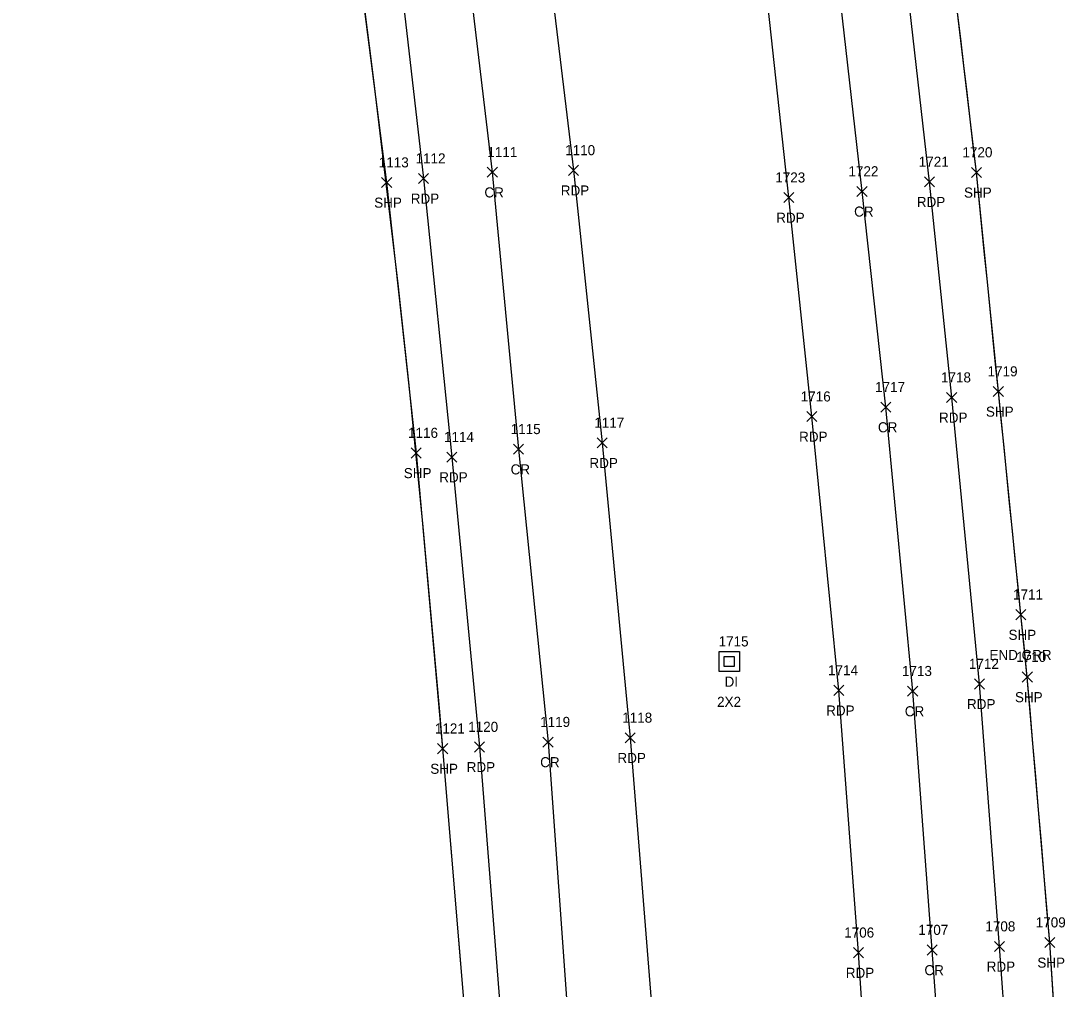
# Model space of a CAD drawing. Extents: x 1472022 to 1479249, y 777216 to 786527.
# Drawn here: x 1473815.7 to 1474023.2, y 781934.6 to 782126.8 of the extents above; entities that cross this region are included whole.
import ezdxf

# ---------------------------------------------------------------- set-up
doc = ezdxf.new("R2010")
doc.units = 0
for name, color, linetype in [('D_A', 7, 'Continuous'), ('D_C', 7, 'Continuous'), ('D_I', 7, 'Continuous'), ('DS', 7, 'Continuous'), ('LSOGP', 7, 'Continuous'), ('P_A', 7, 'Continuous'), ('P_C', 7, 'Continuous'), ('P_I', 7, 'Continuous'), ('P_TIC', 7, 'Continuous'), ('PET', 7, 'Continuous'), ('PRC', 7, 'Continuous'), ('PSP', 7, 'Continuous')]:
    doc.layers.add(name, color=color, linetype=linetype)

msp = doc.modelspace()

# ---------------------------------------------------------------- linework, layer by layer
at = {"layer": 'DS'}
for p, q in [((1473954.34, 782001.6), (1473958.34, 782001.6)), ((1473954.34, 781997.6), (1473954.34, 782001.6)), ((1473955.34, 781998.6), (1473955.34, 782000.6)), ((1473955.34, 782000.6), (1473957.34, 782000.6)), ((1473957.34, 782000.6), (1473957.34, 781998.6)), ((1473958.34, 782001.6), (1473958.34, 781997.6)), ((1473957.34, 781998.6), (1473955.34, 781998.6)), ((1473956.34, 781999.6), (1473956.34, 781999.6)), ((1473956.34, 781999.6), (1473956.34, 781999.6)), ((1473958.34, 781997.6), (1473954.34, 781997.6))]:
    msp.add_line(p, q, dxfattribs=at)
at = {"layer": 'LSOGP'}
for points in [[(1473883.98, 782128.59), (1473884.85, 782121.82), (1473885.71, 782115.04), (1473890.52, 782074.57), (1473891.25, 782067.86), (1473891.98, 782061.15), (1473892.72, 782054.44), (1473895.5, 782026.34), (1473896.16, 782019), (1473896.81, 782011.66), (1473897.47, 782004.33), (1473898.13, 781996.99), (1473898.79, 781989.65), (1473899.44, 781982.31), (1473900.03, 781975.19), (1473900.62, 781968.07), (1473901.21, 781960.95), (1473901.8, 781953.82), (1473902.39, 781946.7), (1473902.98, 781939.58), (1473903.57, 781932.45)], [(1474020.77, 781931.24), (1474020.37, 781937.53), (1474019.96, 781943.82), (1474019.4, 781950.41), (1474018.85, 781957), (1474018.29, 781963.59), (1474017.74, 781970.18), (1474017.18, 781976.76), (1474016.62, 781983.35), (1474016.07, 781989.94), (1474015.51, 781996.53), (1474014.87, 782002.72), (1474014.23, 782008.91), (1474013.67, 782014.45), (1474013.11, 782019.99), (1474012.55, 782025.53), (1474012, 782031.06), (1474011.44, 782036.6), (1474010.88, 782042.14), (1474010.32, 782047.68), (1474009.76, 782053.22), (1474009.21, 782058.66), (1474008.67, 782064.09), (1474008.13, 782069.53), (1474007.58, 782074.97), (1474007.04, 782080.4), (1474006.49, 782085.84), (1474005.95, 782091.28), (1474005.41, 782096.71), (1474004.78, 782102.01), (1474004.16, 782107.31), (1474003.54, 782112.61), (1474002.91, 782117.91), (1474002.29, 782123.21), (1474001.66, 782128.51)]]:
    msp.add_lwpolyline(points, dxfattribs=at)
at = {"layer": 'P_TIC'}
for points in [[(1473908.3, 782095.74), (1473910.3, 782097.74)], [(1473910.3, 782095.74), (1473908.3, 782097.74)], [(1473924.4, 782096.13), (1473926.4, 782098.13)], [(1473926.4, 782096.13), (1473924.4, 782098.13)], [(1474004.41, 782095.71), (1474006.41, 782097.71)], [(1474006.41, 782095.71), (1474004.41, 782097.71)], [(1473887.32, 782093.71), (1473889.32, 782095.71)], [(1473889.32, 782093.71), (1473887.32, 782095.71)], [(1473894.62, 782094.5), (1473896.62, 782096.5)], [(1473896.62, 782094.5), (1473894.62, 782096.5)], [(1473995.08, 782093.84), (1473997.08, 782095.84)], [(1473997.08, 782093.84), (1473995.08, 782095.84)], [(1473981.69, 782091.94), (1473983.69, 782093.94)], [(1473983.69, 782091.94), (1473981.69, 782093.94)], [(1473967.17, 782090.71), (1473969.17, 782092.71)], [(1473969.17, 782090.71), (1473967.17, 782092.71)], [(1474008.76, 782052.22), (1474010.76, 782054.22)], [(1474010.76, 782052.22), (1474008.76, 782054.22)], [(1473999.49, 782051.02), (1474001.49, 782053.02)], [(1474001.49, 782051.02), (1473999.49, 782053.02)], [(1473986.41, 782049.11), (1473988.41, 782051.11)], [(1473988.41, 782049.11), (1473986.41, 782051.11)], [(1473971.71, 782047.23), (1473973.71, 782049.23)], [(1473973.71, 782047.23), (1473971.71, 782049.23)], [(1473930.1, 782042.01), (1473932.1, 782044.01)], [(1473932.1, 782042.01), (1473930.1, 782044.01)], [(1473893.18, 782040.01), (1473895.18, 782042.01)], [(1473895.18, 782040.01), (1473893.18, 782042.01)], [(1473913.5, 782040.75), (1473915.5, 782042.75)], [(1473915.5, 782040.75), (1473913.5, 782042.75)], [(1473900.27, 782039.19), (1473902.27, 782041.19)], [(1473902.27, 782039.19), (1473900.27, 782041.19)], [(1474013.23, 782007.91), (1474015.23, 782009.91)], [(1474015.23, 782007.91), (1474013.23, 782009.91)], [(1474005.04, 781994.15), (1474007.04, 781996.15)], [(1474007.04, 781994.15), (1474005.04, 781996.15)], [(1474014.51, 781995.53), (1474016.51, 781997.53)], [(1474016.51, 781995.53), (1474014.51, 781997.53)], [(1473977.08, 781992.88), (1473979.08, 781994.88)], [(1473979.08, 781992.88), (1473977.08, 781994.88)], [(1473991.75, 781992.73), (1473993.75, 781994.73)], [(1473993.75, 781992.73), (1473991.75, 781994.73)], [(1473905.73, 781981.64), (1473907.73, 781983.64)], [(1473907.73, 781981.64), (1473905.73, 781983.64)], [(1473919.36, 781982.62), (1473921.36, 781984.62)], [(1473921.36, 781982.62), (1473919.36, 781984.62)], [(1473935.65, 781983.46), (1473937.65, 781985.46)], [(1473937.65, 781983.46), (1473935.65, 781985.46)], [(1473898.44, 781981.31), (1473900.44, 781983.31)], [(1473900.44, 781981.31), (1473898.44, 781983.31)], [(1474018.96, 781942.82), (1474020.96, 781944.82)], [(1474020.96, 781942.82), (1474018.96, 781944.82)], [(1473980.98, 781940.8), (1473982.98, 781942.8)], [(1473982.98, 781940.8), (1473980.98, 781942.8)], [(1473995.64, 781941.33), (1473997.64, 781943.33)], [(1473997.64, 781941.33), (1473995.64, 781943.33)], [(1474008.96, 781942.03), (1474010.96, 781944.03)], [(1474010.96, 781942.03), (1474008.96, 781944.03)]]:
    msp.add_lwpolyline(points, dxfattribs=at)
at = {"layer": 'PET'}
for points in [[(1474013.69, 781892.18), (1474009.96, 781943.03), (1474006.04, 781995.15), (1474000.49, 782052.02), (1473996.08, 782094.84), (1473991.19, 782137.97), (1473985.56, 782186.94), (1473979.75, 782232.63), (1473974.58, 782277.36), (1473969.2, 782318.89), (1473964.03, 782360.94), (1473956.61, 782419.72), (1473949.82, 782474.29), (1473942.88, 782526.93), (1473938.67, 782561.99), (1473934.65, 782592.56), (1473928.69, 782642.75), (1473922.69, 782688.94)], [(1473985.44, 781889.72), (1473981.98, 781941.8), (1473978.08, 781993.88), (1473972.71, 782048.23), (1473968.17, 782091.71), (1473963.4, 782135.69), (1473957.31, 782184.57), (1473951.51, 782230.2), (1473946.14, 782274.71), (1473941.19, 782313.76), (1473936.4, 782352.51), (1473927.93, 782415.63), (1473921.17, 782470.8), (1473914.11, 782524.35), (1473909.99, 782558.8), (1473906.05, 782589.71), (1473900.14, 782638.94), (1473894.25, 782685.56)], [(1473853.26, 782678.74), (1473862.81, 782601.91), (1473872.29, 782529.45), (1473878.87, 782478.11), (1473885.04, 782425.74), (1473891.89, 782369.8), (1473898.9, 782316.38), (1473905.27, 782261.68), (1473912.06, 782207.53), (1473918.55, 782154.32), (1473925.4, 782097.13), (1473931.1, 782043.01), (1473936.65, 781984.46), (1473941.26, 781927.31)], [(1473823.32, 782677.22), (1473833.33, 782599.61), (1473842.53, 782526.83), (1473848.75, 782473.74), (1473855.58, 782422.3), (1473862.39, 782366.21), (1473869.18, 782313.85), (1473875.71, 782258.2), (1473882.8, 782203.94), (1473889.42, 782149.71), (1473895.62, 782095.5), (1473901.27, 782040.19), (1473906.73, 781982.64), (1473911.24, 781925.62)]]:
    msp.add_lwpolyline(points, dxfattribs=at)
at = {"layer": 'PRC'}
for points in [[(1474000.48, 781890.51), (1473996.64, 781942.33), (1473992.75, 781993.73), (1473987.41, 782050.11), (1473982.69, 782092.94), (1473977.75, 782136.74), (1473972.62, 782185.34), (1473966.37, 782231.63), (1473961.16, 782276.18), (1473956.15, 782316.84), (1473951.46, 782354.9), (1473943.69, 782417.69), (1473936.64, 782472.53), (1473929.75, 782525.36), (1473925.27, 782560.63), (1473921.44, 782591.12), (1473915.37, 782640.6), (1473907.8, 782687.43)], [(1473836.1, 782681.15), (1473846.69, 782601.05), (1473856.08, 782526.86), (1473862.37, 782475.58), (1473868.64, 782425.17), (1473875.77, 782367.97), (1473882.76, 782314.97), (1473889.35, 782259.54), (1473896.33, 782205.24), (1473902.66, 782152.32), (1473909.3, 782096.74), (1473914.5, 782041.75), (1473920.36, 781983.62), (1473924.52, 781926.3)]]:
    msp.add_lwpolyline(points, dxfattribs=at)
at = {"layer": 'PSP'}
for points in [[(1474023.21, 781893.51), (1474019.96, 781943.82), (1474015.51, 781996.53), (1474014.23, 782008.91), (1474009.76, 782053.22), (1474005.41, 782096.71), (1474000.42, 782139.1), (1473994.67, 782187.68), (1473988.77, 782234.07), (1473983.65, 782278.85), (1473978.42, 782321.78), (1473973.33, 782361.06), (1473966.01, 782421.25), (1473959.18, 782474.93), (1473952.46, 782528.67), (1473948.21, 782563.48), (1473944.2, 782593.52), (1473937.62, 782642.8), (1473931.59, 782689.38)], [(1473815.72, 782675.07), (1473824.83, 782598.85), (1473833.44, 782525.48), (1473840.22, 782472.27), (1473847.17, 782419.46), (1473853.65, 782365.53), (1473860.83, 782312.43), (1473867.42, 782257.22), (1473874.03, 782203.74), (1473881.37, 782148.92), (1473888.32, 782094.71), (1473894.18, 782041.01), (1473899.44, 781982.31), (1473904.16, 781925.33)]]:
    msp.add_lwpolyline(points, dxfattribs=at)

# ---------------------------------------------------------------- texts
at = {"layer": 'D_A'}
msp.add_text('DI', height=2, dxfattribs=at).set_placement((1473955.4, 781994.6))
at = {"layer": 'D_C'}
msp.add_text('2X2', height=2, dxfattribs=at).set_placement((1473953.92, 781990.6))
at = {"layer": 'D_I'}
msp.add_text('1715', height=2, dxfattribs=at).set_placement((1473954.22, 782002.6))
at = {"layer": 'P_A'}
for s, p in [('CR', (1473907.73, 782091.74)), ('RDP', (1473922.89, 782092.13)), ('SHP', (1474002.94, 782091.71)), ('SHP', (1473885.85, 782089.71)), ('RDP', (1473893.11, 782090.5)), ('RDP', (1473993.57, 782089.84)), ('CR', (1473981.12, 782087.94)), ('RDP', (1473965.66, 782086.71)), ('SHP', (1474007.29, 782048.22)), ('RDP', (1473997.98, 782047.02)), ('CR', (1473985.85, 782045.11)), ('RDP', (1473970.2, 782043.23)), ('RDP', (1473928.58, 782038.01)), ('SHP', (1473891.72, 782036.01)), ('CR', (1473912.93, 782036.75)), ('RDP', (1473898.76, 782035.19)), ('SHP', (1474011.77, 782003.91)), ('RDP', (1474003.53, 781990.15)), ('SHP', (1474013.05, 781991.53)), ('RDP', (1473975.57, 781988.88)), ('CR', (1473991.18, 781988.73)), ('RDP', (1473934.14, 781979.46)), ('RDP', (1473904.21, 781977.64)), ('CR', (1473918.8, 781978.62)), ('SHP', (1473896.98, 781977.31)), ('RDP', (1474007.44, 781938.03)), ('SHP', (1474017.5, 781938.82)), ('RDP', (1473979.47, 781936.8)), ('CR', (1473995.08, 781937.33))]:
    msp.add_text(s, height=2, dxfattribs=at).set_placement(p)
at = {"layer": 'P_C'}
msp.add_text('END GRR', height=2, dxfattribs=at).set_placement((1474007.99, 781999.91))
at = {"layer": 'P_I'}
for s, p in [('1110', (1473923.76, 782100.13)), ('1113', (1473886.76, 782097.71)), ('1112', (1473894.06, 782098.5)), ('1111', (1473908.31, 782099.74)), ('1721', (1473993.96, 782097.84)), ('1720', (1474002.63, 782099.71)), ('1722', (1473980, 782095.94)), ('1723', (1473965.47, 782094.71)), ('1719', (1474007.62, 782056.22)), ('1718', (1473998.37, 782055.02)), ('1717', (1473985.29, 782053.11)), ('1716', (1473970.53, 782051.23)), ('1117', (1473929.54, 782046.01)), ('1116', (1473892.57, 782044.01)), ('1115', (1473912.94, 782044.75)), ('1114', (1473899.71, 782043.19)), ('1711', (1474012.67, 782011.91)), ('1712', (1474003.91, 781998.15)), ('1710', (1474013.3, 781999.53)), ('1714', (1473975.96, 781996.88)), ('1713', (1473990.62, 781996.73)), ('1120', (1473904.51, 781985.64)), ('1119', (1473918.8, 781986.62)), ('1118', (1473935.09, 781987.46)), ('1121', (1473897.89, 781985.31)), ('1709', (1474017.18, 781946.82)), ('1706', (1473979.16, 781944.8)), ('1707', (1473993.87, 781945.33)), ('1708', (1474007.18, 781946.03))]:
    msp.add_text(s, height=2, dxfattribs=at).set_placement(p)

doc.saveas('drawing.dxf')
